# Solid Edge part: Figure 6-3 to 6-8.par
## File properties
Author: CADCIM
Template: Iso Part.par
Last saved by: CADCIM
Revision: 3
Application: Solid Edge
Accuracy: 0.990
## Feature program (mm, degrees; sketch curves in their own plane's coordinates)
sketch for "Hole_1" plane through (0, 0, 44.0811) normal (0, 0, 1) x-axis (1, 0, 0)
  hole centre (-0.8799, 3.0796) bore radius 27.5
hole "Hole_1" diameter 55 finite  CounterSinkAngle = 82 deg
pattern "unnamed Pattern 1" of "Hole_1"
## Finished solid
Body 1: solid body, 6 faces, 6 edges, 0 vertices.
  Faces by surface: cylinder 3, plane 2, cone 1
  Edges by curve: circle 6
Bounding box of the edges (mm): 114.624 x 114.624 x 88.162, from (-57.3122, -57.3122, -44.0811) to (57.3122, 57.3122, 44.0811).
Cylindrical faces by radius (mm): R27.5 x1, R32.5 x1, R57.3122 x1
Conical faces (half-angle, radius in mm at the cone's reference point): 41 deg R32.5 x1
Planar faces by outward normal: +z 1, -z 1
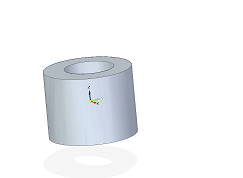
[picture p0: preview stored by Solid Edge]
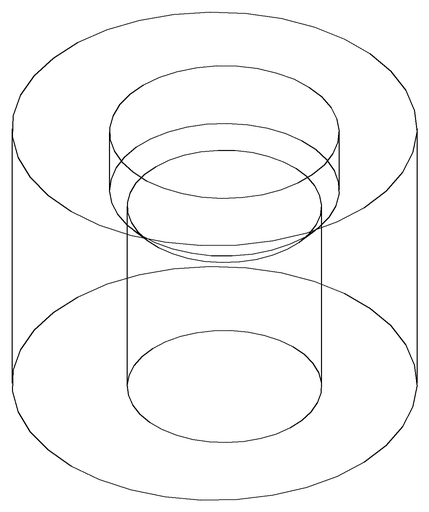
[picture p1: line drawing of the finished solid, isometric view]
